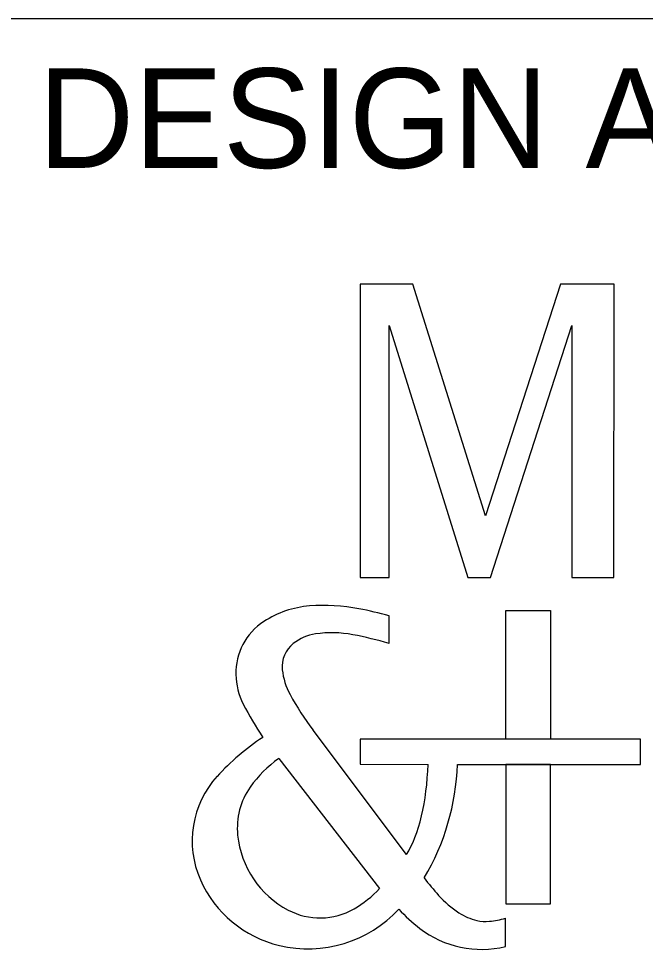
# Model space of a CAD drawing. Extents: x 0 to 34, y 0 to 22.
# Drawn here: x 32.03 to 32.66, y 3.565 to 4.5 of the extents above; entities that cross this region are included whole.
import ezdxf

# ---------------------------------------------------------------- set-up
doc = ezdxf.new("R2010")
doc.units = 0
doc.layers.add('SH_Border', color=7, linetype='Continuous')
doc.layers.add('SH_Data', color=7, linetype='Continuous')

msp = doc.modelspace()

# ---------------------------------------------------------------- linework, layer by layer
at = {"layer": 'SH_Border'}
msp.add_line((32, 4.5), (33.5, 4.5), dxfattribs=at)
at = {"layer": 'SH_Data'}
for p, q in [((32.51964, 3.7761), (32.51968, 3.90518)), ((32.51968, 3.90518), (32.56466, 3.90516)), ((32.56466, 3.90516), (32.56461, 3.7761)), ((32.40255, 3.87202), (32.40255, 3.89973)), ((32.42004, 3.66009), (32.32622, 3.78489)), ((32.29164, 3.75653), (32.39287, 3.62592)), ((32.51963, 3.75061), (32.51958, 3.61052)), ((32.5646, 3.7506), (32.51963, 3.75061)), ((32.56455, 3.6105), (32.5646, 3.7506)), ((32.22973, 3.73843), (32.22995, 3.73868)), ((32.51958, 3.61052), (32.56455, 3.6105)), ((32.51943, 3.56761), (32.51954, 3.596))]:
    msp.add_line(p, q, dxfattribs=at)
msp.add_lwpolyline([(32.40256, 3.93855), (32.40265, 4.19174), (32.48171, 3.93852), (32.50421, 3.93851), (32.58601, 4.19168), (32.58592, 3.93848), (32.62836, 3.93847), (32.62847, 4.23313), (32.57462, 4.23315), (32.49947, 4.00037), (32.42651, 4.2332), (32.37346, 4.23322), (32.37335, 3.93856)], close=True, dxfattribs=at)
msp.add_lwpolyline([(32.40256, 3.93855), (32.40265, 4.19174), (32.48171, 3.93852), (32.50421, 3.93851), (32.58601, 4.19168), (32.58592, 3.93848), (32.62836, 3.93847), (32.62847, 4.23313), (32.57462, 4.23315), (32.49947, 4.00037), (32.42651, 4.2332), (32.37346, 4.23322), (32.37335, 3.93856)], close=True, dxfattribs=at)
msp.add_lwpolyline([(32.47111, 3.75063), (32.65487, 3.75056), (32.65487, 3.7761), (32.37332, 3.7761), (32.37332, 3.75067), (32.44161, 3.75064)], dxfattribs=at)
for centre, radius, start, end in [((32.33027, 3.812), 0.09807, 94.52064, 123.10613), ((32.33713, 3.72528), 0.18506, 79.05632, 94.52064), ((32.30456, 3.55685), 0.35661, 74.05158, 79.05632), ((32.31056, 3.84222), 0.06199, 123.10613, 181.21524), ((32.33549, 3.8351), 0.04707, 98.37229, 128.32899), ((32.34512, 3.76964), 0.11323, 79.2666, 98.37229), ((32.29951, 3.52901), 0.35815, 73.28029, 79.2666), ((32.32459, 3.84889), 0.02949, 128.32899, 186.08207), ((32.36146, 3.85282), 0.06657, 186.08207, 208.5769), ((32.31692, 3.84236), 0.06835, 181.21524, 207.10908), ((32.56161, 3.96184), 0.29448, 208.5769, 216.93296), ((32.56702, 3.97039), 0.34932, 207.10908, 213.46559), ((32.41281, 3.57127), 0.24792, 123.60001, 137.60346), ((32.36078, 3.65921), 0.11938, 125.39274, 144.90419), ((32.23306, 3.7584), 0.23818, 329.23556, 358.13143), ((32.30118, 3.67365), 0.09645, 137.60346, 203.9313), ((32.32173, 3.68665), 0.07165, 144.90419, 185.75539), ((32.34593, 3.68909), 0.09598, 185.75539, 242.15282), ((32.31906, 3.68158), 0.11601, 203.9313, 256.6813), ((32.63282, 3.78323), 0.24407, 216.93296, 222.28978), ((32.3133, 3.69909), 0.1081, 299.979, 317.39916), ((32.53229, 3.69179), 0.10818, 222.28978, 236.57616), ((32.32103, 3.6899), 0.12456, 256.6813, 317.10886), ((32.33309, 3.66478), 0.06849, 242.15282, 299.979), ((32.53702, 3.72017), 0.16969, 222.68498, 232.35251), ((32.50304, 3.64747), 0.05509, 236.57616, 256.97276), ((32.49975, 3.63322), 0.04046, 256.97276, 275.06378), ((32.49598, 3.67574), 0.08315, 275.06378, 286.4619), ((32.49531, 3.6661), 0.1014, 232.35251, 283.76294)]:
    msp.add_arc(centre, radius, start, end, dxfattribs=at)
msp.add_ellipse((32.40096, 3.7518), major_axis=(-0.00307, -0.10769), ratio=0.377453, start_param=0.562501, end_param=1.570796, dxfattribs=at)

# ---------------------------------------------------------------- texts
msp.add_text('DESIGN AGENCY', height=0.1, dxfattribs=at).set_placement((32.05, 4.35))

doc.saveas('drawing.dxf')
